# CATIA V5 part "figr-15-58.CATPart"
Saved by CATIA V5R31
Part number: Part1
Bounding box of the stored display mesh (mm): x -20 to 20, y -25 to 25, z 0 to 50
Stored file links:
  D:\PROJECTS\Project 2021\US EDITION\CATIA V5 6R 2021\Resources\Part Files\c15_catia_v5_6r2021_prt\figr-15-58.CATPart
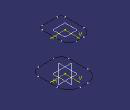
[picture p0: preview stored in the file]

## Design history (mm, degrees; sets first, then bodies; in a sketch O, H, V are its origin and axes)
SheetMetalParameters1: Thickness 2, BendRadius 4, KFactor 0.400515 {= log(min(100,max(20*SheetMetalParameters1.BendRadius,SheetMetalParameters1.Thickness)/SheetMetalParameters1.Thickness))/log(100)/2}, ReliefRadialLength 1, ReliefAxialLength 2, MinimumBendRadius 0
Body1 (main body)
  Plane1: type Offset, RefPlane xy-plane, Offset 50
  Sketch1 on xy-plane, origin (0, 0, 0), H (1, 0, 0), V (0, 1, 0)
    line L1 (20, 10) -> (20, -15)
    line L2 (10, -25) -> (-10, -25)
    line L3 (-20, -15) -> (-20, 10)
    line L4 (-5, 25) -> (5, 25)
    arc A1 centre (5, 10) radius 15 from (20, 10) to (5, 25) ccw
    arc A2 centre (-5, 10) radius 15 from (-20, 10) to (-5, 25) cw
    arc A3 centre (10, -15) radius 10 from (20, -15) to (10, -25) cw
    arc A4 centre (-10, -15) radius 10 from (-10, -25) to (-20, -15) cw
    radius A1 = 15
    radius A2 = 15
    radius A3 = 10
    radius A4 = 10
    distance L4 L2 = 50
    distance L3 L1 = 40
    vertical: L1 V, L3 V
    horizontal: L2 H, L4 H
    equidistance: L1 L3 O, L2 L4 O
    tangency: A1 L1, A1 L4, A2 L3, A2 L4, A3 L1, A3 L2, A4 L2, A4 L3
  Sketch2 on Plane1, origin (0, 0, 50), H (1, 0, 0), V (0, 1, 0)
    line L1 (15, 10) -> (15, -15)
    line L2 (10, -20) -> (-10, -20)
    line L3 (-15, -15) -> (-15, 10)
    line L4 (-5, 20) -> (5, 20)
    arc A1 centre (5, 10) radius 10 from (15, 10) to (5, 20) ccw
    arc A2 centre (10, -15) radius 5 from (15, -15) to (10, -20) cw
    arc A3 centre (-10, -15) radius 5 from (-10, -20) to (-15, -15) cw
    arc A4 centre (-5, 10) radius 10 from (-15, 10) to (-5, 20) cw
    radius A1 = 10
    radius A2 = 5
    radius A3 = 5
    radius A4 = 10
    distance L4 L2 = 40
    distance L1 L3 = 30
    vertical: L1 V, L3 V
    horizontal: L2 H, L4 H
    equidistance: L1 L3 O, L2 L4 O
    tangency: A1 L1, A1 L4, A2 L1, A2 L2, A3 L2, A3 L3, A4 L3, A4 L4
